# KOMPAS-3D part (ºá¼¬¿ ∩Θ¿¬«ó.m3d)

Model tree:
1. Эскиз:1
2. Операция выдавливания:1
     Расстояние 1 = 0.1; Расстояние 2 = 1
3. Смещенная плоскость:1
     Расстояние = 2
4. Эскиз:2
5. Операция выдавливания:2
     Расстояние 1 = 0.1; Расстояние 2 = 0.5
6. Эскиз:3
7. Вырезать элемент выдавливания:1
     Расстояние 1 = 7
8. Эскиз:4
9. Операция выдавливания:3
     Расстояние 1 = 0.2; Расстояние 2 = 0.5
10. Скругление:1
     Радиус = 0.5
11. Эскиз:5
12. Операция выдавливания:4
     Расстояние 1 = 0.2; Расстояние 2 = 4.9
13. Эскиз:6
14. Вырезать элемент выдавливания:2
     Расстояние 1 = 7

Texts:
  Сплав АЛ8  ГОСТ 1583-93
